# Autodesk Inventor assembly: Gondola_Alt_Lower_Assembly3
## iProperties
Shininess: 64.0
Length Units: 11272
Angle Units: 11279
Time Units: 11290
Mass Units: 11286
Length Display Precision: 3
Angle Display Precision: 2
Compacted: True
Part Number: Gondola_Alt_Lower_Assembly3
Document SubType Name: Assembly
Created: 2005-05
Designer: John Blackburn
Manufacturer: Standard
Standards Organization: Custom
Density: 0.0
Volumn: 0.0
Area: 0.0
PropertySet Name: Model Information
Control State: 0
Master: False
Checked Out: False
Author: John Blackburn
